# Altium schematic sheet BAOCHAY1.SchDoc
size A; SheetNumber: 1; SheetTotal: 1
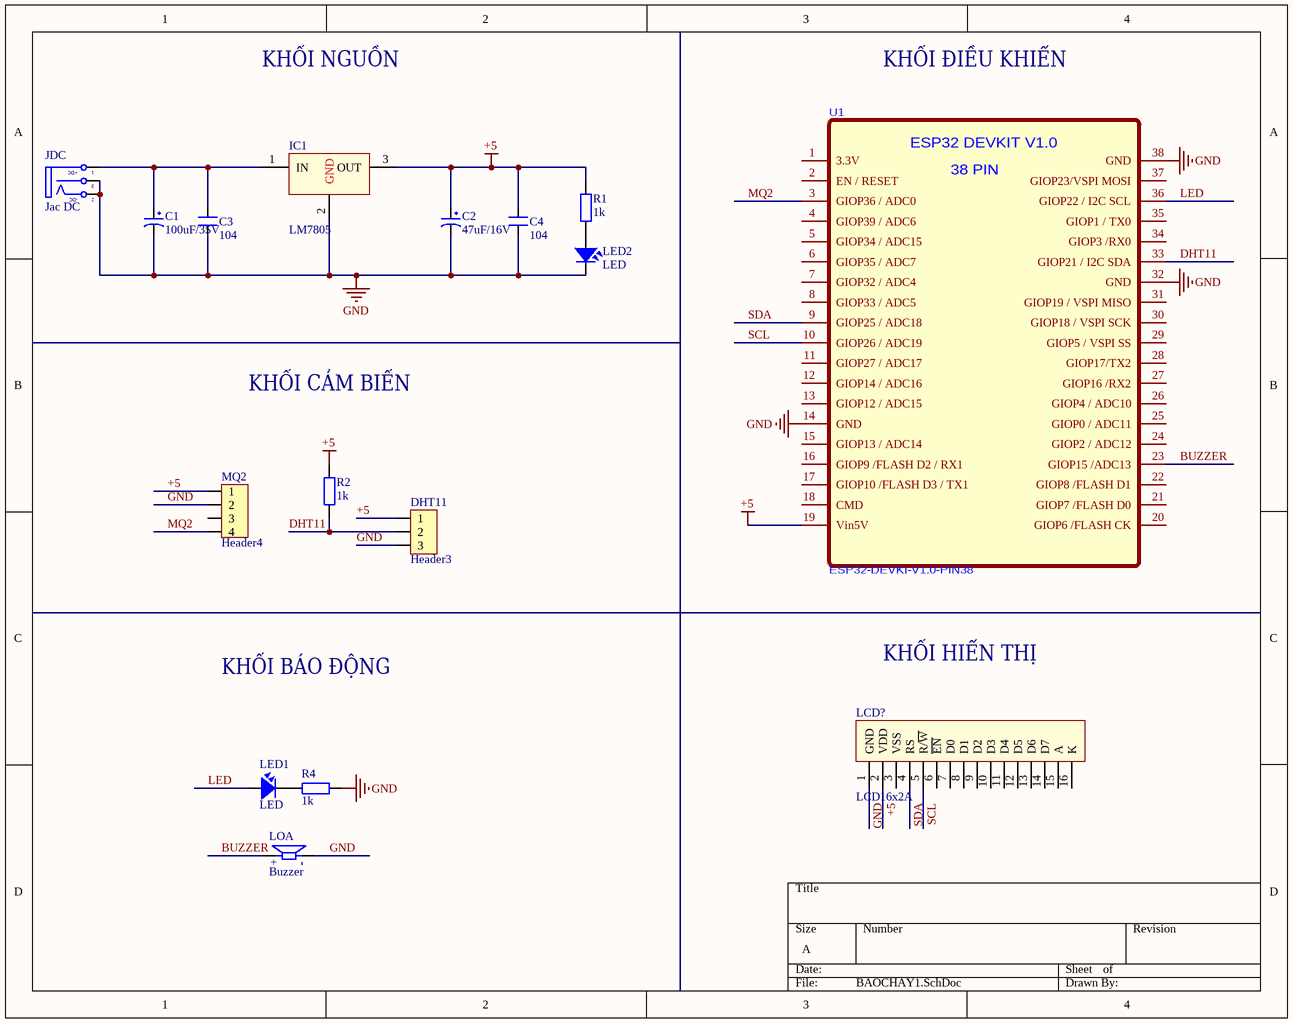
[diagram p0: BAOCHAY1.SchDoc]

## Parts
C1  100uF/35V  [CP1/2.5]
C2  47uF/16V  [CP1/2.5]
C3  104  [CN1]
C4  104  [CN1]
DHT11  Header3  [Header3]
IC1  LM7805  [QTO-220]
JDC  Jac DC  [DC-IN]
LCD?  LCD16x2A  [LCD16X2]
LED1  LED  [LED-3]
LED2  LED  [LED-3]
LOA  Buzzer  [Buzzer-9MM]
MQ2  Header4  [Header4]
R1  1k  [R1/4W]
R2  1k  [R1/4W]
R4  1k  [R1/4W]
U1  ESP32-DEVKI-V1.0-PIN38  [ESP32-DEVKIT-V1.0-38PIN]

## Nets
+5: C2.1 C4.2 DHT11.1 IC1.3(OUT) LCD?.2(VDD) MQ2.1 R1.2 R2.1 U1.19(Vin5V)
GND: C1.2 C2.2 C3.1 C4.1 DHT11.3 IC1.2(GND) JDC.2(TN) JDC.3(S) LCD?.1(GND) LED2.2 LOA.2(M) MQ2.2 R4.2 U1.14(GND) U1.32(GND) U1.38(GND)
BUZZER: LOA.1(P) U1.23(GIOP15_/ADC13)
DHT11: DHT11.2 R2.2 U1.33(GIOP21_/_I2C_SDA)
LED: LED1.1 U1.36(GIOP22_/_I2C_SCL)
MQ2: MQ2.4 U1.3(GIOP36_/_ADC0)
SCL: LCD?.5(R/~{W}) U1.10(GIOP26_/_ADC19)
SDA: LCD?.4(RS) U1.9(GIOP25_/_ADC18)
NetC1_1: C1.1 C3.2 IC1.1(IN) JDC.1(T)
NetLED1_2: LED1.2 R4.1
NetLED2_1: LED2.1 R1.1

Not connected (* = marked no-connect by the designer): LCD? 3(VSS) 6(~{EN}) 7(D0) 8(D1) 9(D2) 10(D3) 11(D4) 12(D5) 13(D6) 14(D7) 15(A) 16(K); MQ2 3; U1 1(3.3V) 2(EN_/_RESET) 4(GIOP39_/_ADC6) 5(GIOP34_/_ADC15) 6(GIOP35_/_ADC7) 7(GIOP32_/_ADC4) 8(GIOP33_/_ADC5) 11(GIOP27_/_ADC17) 12(GIOP14_/_ADC16) 13(GIOP12_/_ADC15) 15(GIOP13_/_ADC14) 16(GIOP9_/FLASH_D2_/_RX1) 17(GIOP10_/FLASH_D3_/_TX1) 18(CMD) 20(GIOP6_/FLASH_CK) 21(GIOP7_/FLASH_D0) 22(GIOP8_/FLASH_D1) 24(GIOP2_/_ADC12) 25(GIOP0_/_ADC11) 26(GIOP4_/_ADC10) 27(GIOP16_/RX2) 28(GIOP17/TX2) 29(GIOP5_/_VSPI_SS) 30(GIOP18_/_VSPI_SCK) 31(GIOP19_/_VSPI_MISO) 34(GIOP3_/RX0) 35(GIOP1_/_TX0) 37(GIOP23/VSPI_MOSI)

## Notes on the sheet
- KHỐI NGUỒN
- KHỐI ĐIỀU KHIỂN
- KHỐI CẢM BIẾN
- KHỐI BÁO ĐỘNG
- KHỐI HIỂN THỊ

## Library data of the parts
C1 C2 = CP2: C 47uF/50V , 220uF/16V; Value: 47uF/16 - 50V; Description 1: 470uF/6,3V - 330uF/10V - 220uF/16V; Description 2: 100uF/25V - 35V - 47uF/50V - 22uF/100V; Description 3: 33uF => 47uF/63V - 1uF => 4,7uF/160V; Description 4: 1uF => 2,2uF/250V - 1uF/350V
C3 C4 = CN1: Cap np  1pF - 472pF; Value: 100pF
DHT11 = Header3: Header IDC, 3 x 1 Pin Vertical 2.54mm Pitch (Non-Boxed, Male); Manufacturer: W¨¹rth Elektronik eiSos GmbH; partNo: 613002143121; ComponentLink1 Description: Manufacturer; ComponentLink2 Description: Datasheet; NoPins: 02
IC1 = LM78xx: On ap +, from + 5 to + 24VDC
JDC = DCIN: Jac DC input
LCD? = LCD16x2: LCD dipslay 16 char, 2 line
LED1 LED2 = LED: LED Single colour Green and Red; Value: LED 3 ly Single Colour
LOA = Buzzer: MP: CST-951AP
MQ2 = Header4: Header IDC, 4 x 1 Pin Vertical 2.54mm Pitch (Non-Boxed, Male); Manufacturer: W¨¹rth Elektronik eiSos GmbH; partNo: 613002143121; ComponentLink1 Description: Manufacturer; ComponentLink2 Description: Datasheet; NoPins: 02
R1 R2 R4 = R1/4W: Resistor 1/4W; Value: R1/4W - 1K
